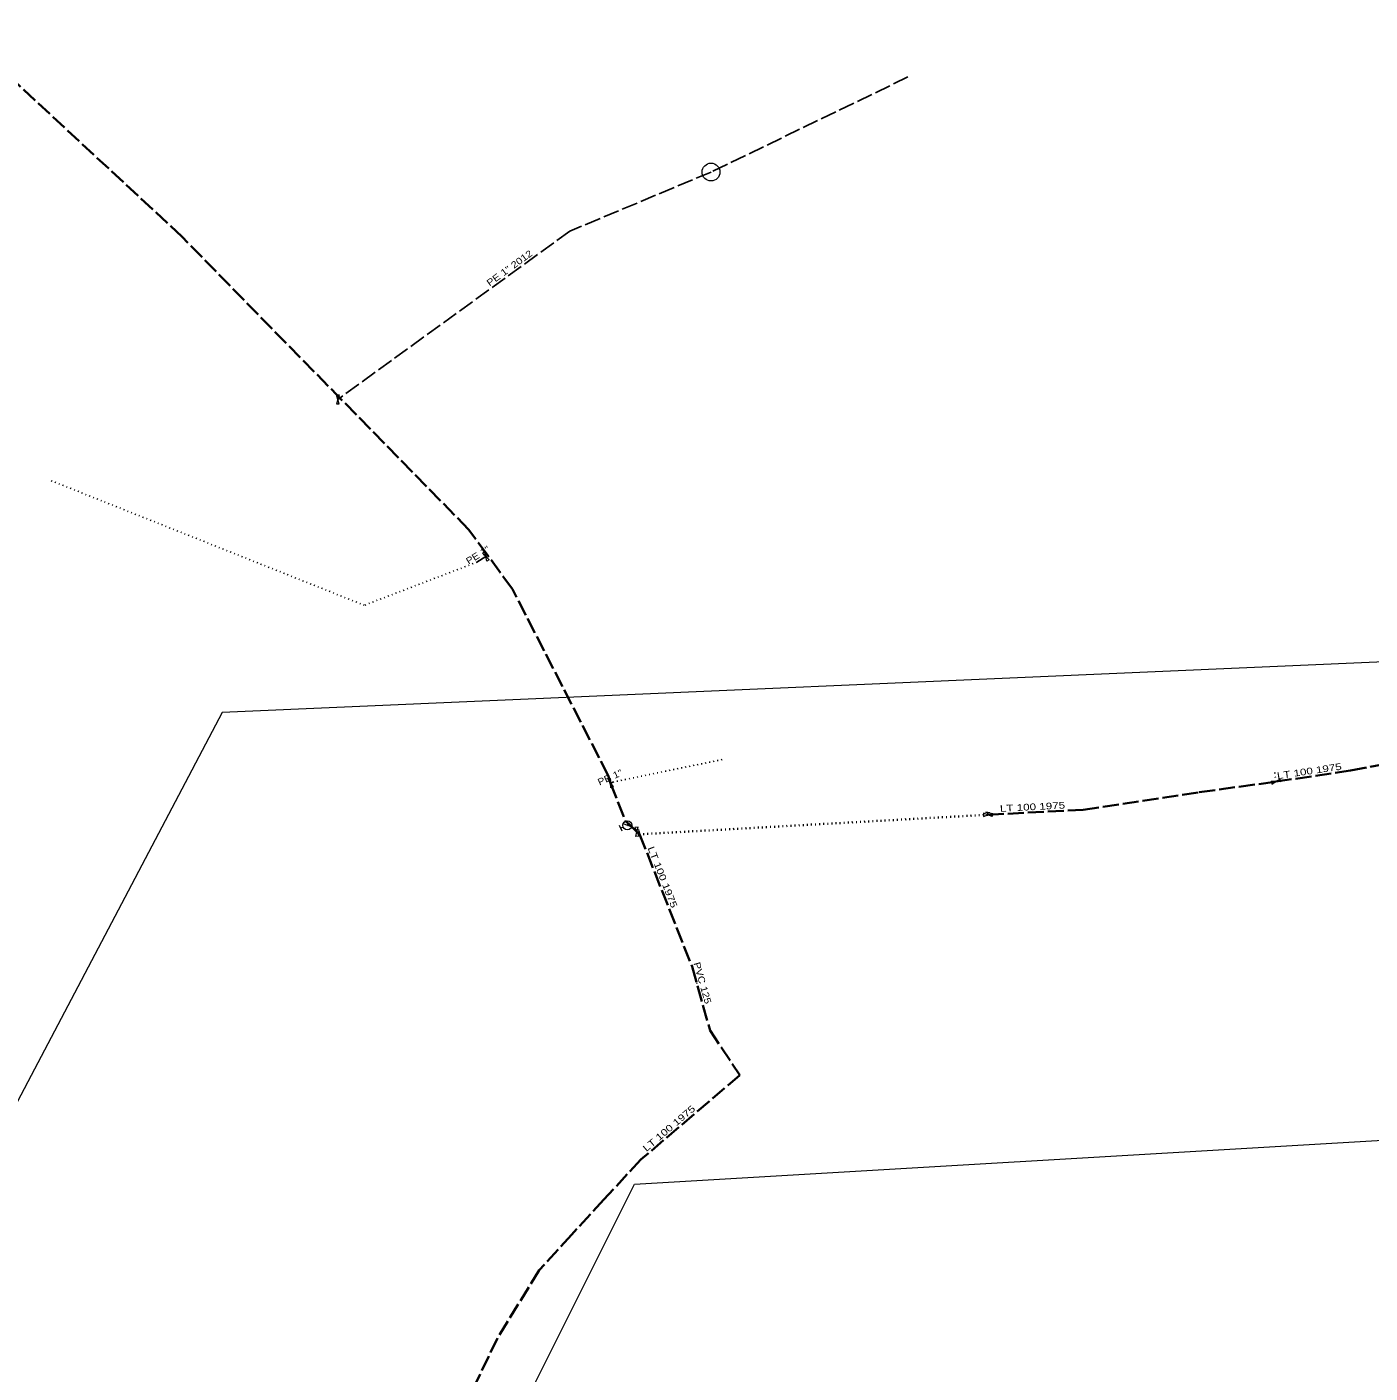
# Model space of a CAD drawing. Extents: x -582626 to -580899, y -1097611 to -1096610.
# Drawn here: x -581390.7 to -581240, y -1096761 to -1096610 of the extents above; entities that cross this region are included whole.
import ezdxf
from ezdxf.enums import TextEntityAlignment as Align

# ---------------------------------------------------------------- set-up
doc = ezdxf.new("R2010")
doc.units = 0
doc.header["$LTSCALE"] = 0.3
for name, pattern in [('DASH_DOUBLE_DOT', [9.2, 5, -1.2, 0.3, -1.2, 0.3, -1.2]), ('DOTTED', [1.5, 0.3, -1.2]), ('LONG_DASHED', [7.5, 6, -1.5])]:
    doc.linetypes.add(name, pattern=pattern)
for name, color, linetype, lineweight in [('1', 7, 'Continuous', 13), ('10', 7, 'Continuous', 13), ('26', 7, 'DASH_DOUBLE_DOT', 13), ('35', 7, 'LONG_DASHED', 35), ('36', 7, 'DASH_DOUBLE_DOT', 35), ('50', 7, 'LONG_DASHED', 25), ('51', 7, 'DOTTED', 25)]:
    doc.layers.add(name, color=color, linetype=linetype, lineweight=lineweight)
for name, color, linetype in [('16', 7, 'Continuous'), ('19', 7, 'Continuous'), ('20', 7, 'Continuous')]:
    doc.layers.add(name, color=color, linetype=linetype)

msp = doc.modelspace()

# ---------------------------------------------------------------- linework, layer by layer
at = {"layer": '1'}
msp.add_lwpolyline([(-582625.57, -1097394.66), (-582612.34, -1097467.421), (-582321.299, -1097262.369), (-581897.965, -1097202.837), (-581719.372, -1097182.994), (-581593.695, -1097110.233), (-581382.028, -1096971.327), (-581362.184, -1096819.192), (-581322.497, -1096739.817), (-581210.049, -1096733.202), (-581097.601, -1096686.9), (-580905.778, -1096719.973), (-580899.163, -1096627.369), (-581084.372, -1096614.14), (-581216.663, -1096680.285), (-581368.799, -1096686.9), (-581434.945, -1096812.577), (-581468.018, -1096971.327), (-581659.84, -1097004.4), (-581831.82, -1097110.233), (-582314.684, -1097169.765), (-582519.736, -1097295.442), (-582625.57, -1097394.66)], close=True, dxfattribs=at)
at = {"layer": '10'}
for p, q in [((-581282.851, -1096698.132), (-581283.101, -1096698.132)), ((-581323.89, -1096700.22), (-581324.18, -1096699.583)), ((-581323.762, -1096699.777), (-581324.035, -1096699.902)), ((-581322.838, -1096699.745), (-581323.775, -1096699.395)), ((-581321.988, -1096700.27), (-581322.018, -1096700.022))]:
    msp.add_line(p, q, dxfattribs=at)
for points in [[(-581355.813, -1096651.788), (-581355.963, -1096651.288), (-581355.663, -1096651.288), (-581355.813, -1096651.788), (-581355.963, -1096652.288), (-581355.663, -1096652.288)], [(-581339.18, -1096669.418), (-581338.808, -1096669.785), (-581339.071, -1096669.929), (-581339.18, -1096669.418), (-581339.289, -1096668.907), (-581339.552, -1096669.051)], [(-581325.188, -1096694.839), (-581324.894, -1096695.27), (-581325.18, -1096695.361), (-581325.188, -1096694.839), (-581325.196, -1096694.317), (-581325.482, -1096694.408)], [(-581250.542, -1096694.672), (-581250.097, -1096694.399), (-581250.02, -1096694.69), (-581250.542, -1096694.672), (-581251.064, -1096694.654), (-581250.987, -1096694.945)]]:
    msp.add_lwpolyline(points, close=True, dxfattribs=at)
for points in [[(-581282.851, -1096698.382), (-581282.351, -1096698.195), (-581282.351, -1096698.569), (-581282.851, -1096698.382), (-581283.351, -1096698.195), (-581283.351, -1096698.569), (-581282.851, -1096698.382), (-581282.851, -1096698.132), (-581282.601, -1096698.132)], [(-581322.236, -1096700.3), (-581321.991, -1096700.774), (-581322.362, -1096700.819), (-581322.236, -1096700.3), (-581322.11, -1096699.781), (-581322.481, -1096699.826), (-581322.236, -1096700.3), (-581321.988, -1096700.27), (-581321.958, -1096700.518)]]:
    msp.add_lwpolyline(points, dxfattribs=at)
for centre, radius in [((-581313.918, -1096626.284), 1), ((-581323.3073, -1096699.5699), 0.5)]:
    msp.add_circle(centre, radius, dxfattribs=at)
at = {"layer": '26'}
msp.add_line((-581316.045, -1096715.422), (-581314.96, -1096719.246), dxfattribs=at)
at = {"layer": '35'}
for p, q in [((-581325.452, -1096693.991), (-581325.188, -1096694.839)), ((-581321.931, -1096700.577), (-581322.24, -1096700.31))]:
    msp.add_line(p, q, dxfattribs=at)
for points in [[(-581338.976, -1096669.3), (-581341.123, -1096666.369), (-581373.277, -1096633.554), (-581397.534, -1096611.01), (-581399.786, -1096610.001)], [(-581282.851, -1096698.382), (-581272.164, -1096697.829), (-581259.131, -1096695.863), (-581250.542, -1096694.672), (-581242.143, -1096693.432), (-581236.734, -1096692.413), (-581231.902, -1096691.503), (-581210.162, -1096686.212), (-581188.602, -1096679.388), (-581176.072, -1096674.108), (-581163.45, -1096667.317), (-581155.012, -1096661.891), (-581145.313, -1096656.011), (-581131.766, -1096648.598), (-581129.767, -1096647.793), (-581129.897, -1096646.337), (-581129.983, -1096645.369)], [(-581325.452, -1096693.991), (-581336.213, -1096673.071), (-581338.976, -1096669.3)], [(-581325.188, -1096694.839), (-581323.527, -1096699.101), (-581323.082, -1096699.462)], [(-581323.307, -1096699.57), (-581323.082, -1096699.462), (-581322.236, -1096700.3)], [(-581321.931, -1096700.577), (-581316.045, -1096715.422), (-581314.027, -1096722.581), (-581310.681, -1096727.605), (-581321.786, -1096737.077), (-581325.934, -1096741.538), (-581329.57, -1096745.504), (-581333.191, -1096749.465), (-581337.882, -1096757.099), (-581343.31, -1096768.311)]]:
    msp.add_lwpolyline(points, dxfattribs=at)
at = {"layer": '36', "linetype": 'DOTTED'}
msp.add_line((-581282.851, -1096698.382), (-581321.931, -1096700.577), dxfattribs=at)
at = {"layer": '50'}
msp.add_line((-581325.188, -1096694.839), (-581324.925, -1096694.722), dxfattribs=at)
for points in [[(-581291.824, -1096615.618), (-581313.918, -1096626.284), (-581329.747, -1096632.905), (-581355.813, -1096651.788)], [(-581340.201, -1096670.05), (-581339.18, -1096669.418), (-581338.976, -1096669.3)]]:
    msp.add_lwpolyline(points, dxfattribs=at)
at = {"layer": '51'}
for p, q in [((-581324.925, -1096694.722), (-581312.499, -1096692.155)), ((-581250.542, -1096694.672), (-581250.659, -1096693.431))]:
    msp.add_line(p, q, dxfattribs=at)
msp.add_lwpolyline([(-581340.201, -1096670.05), (-581352.827, -1096674.886), (-581388.191, -1096660.824)], dxfattribs=at)

# ---------------------------------------------------------------- texts
at = {"layer": '16', "width": 1.3}
for rotation, p in [(8.398, (-581246.7228, -1096693.8557)), (2.962, (-581277.8199, -1096697.8711)), (291.628, (-581319.7011, -1096705.5188)), (40.462, (-581318.3929, -1096733.8536))]:
    msp.add_text('LT 100 1975', height=0.75, rotation=rotation, dxfattribs=at).set_placement(p, align=Align.CENTER)
at = {"layer": '19'}
for s, rotation, width, p in [('PE 1" 2012', 35.921, 1.2, (-581336.316, -1096637.3555)), ('PE 1"', 31.758, 1.15, (-581339.8874, -1096669.5611)), ('PE 1"', 23.983, 1.15, (-581325.1009, -1096694.527))]:
    msp.add_text(s, height=0.75, rotation=rotation, dxfattribs=dict(at, width=width)).set_placement(p, align=Align.CENTER)
at = {"layer": '20', "width": 1.2}
msp.add_text('PVC 125', height=0.75, rotation=285.84, dxfattribs=at).set_placement((-581315.2364, -1096717.3566), align=Align.CENTER)

doc.saveas('drawing.dxf')
